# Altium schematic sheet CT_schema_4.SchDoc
size 382 x 218 mm
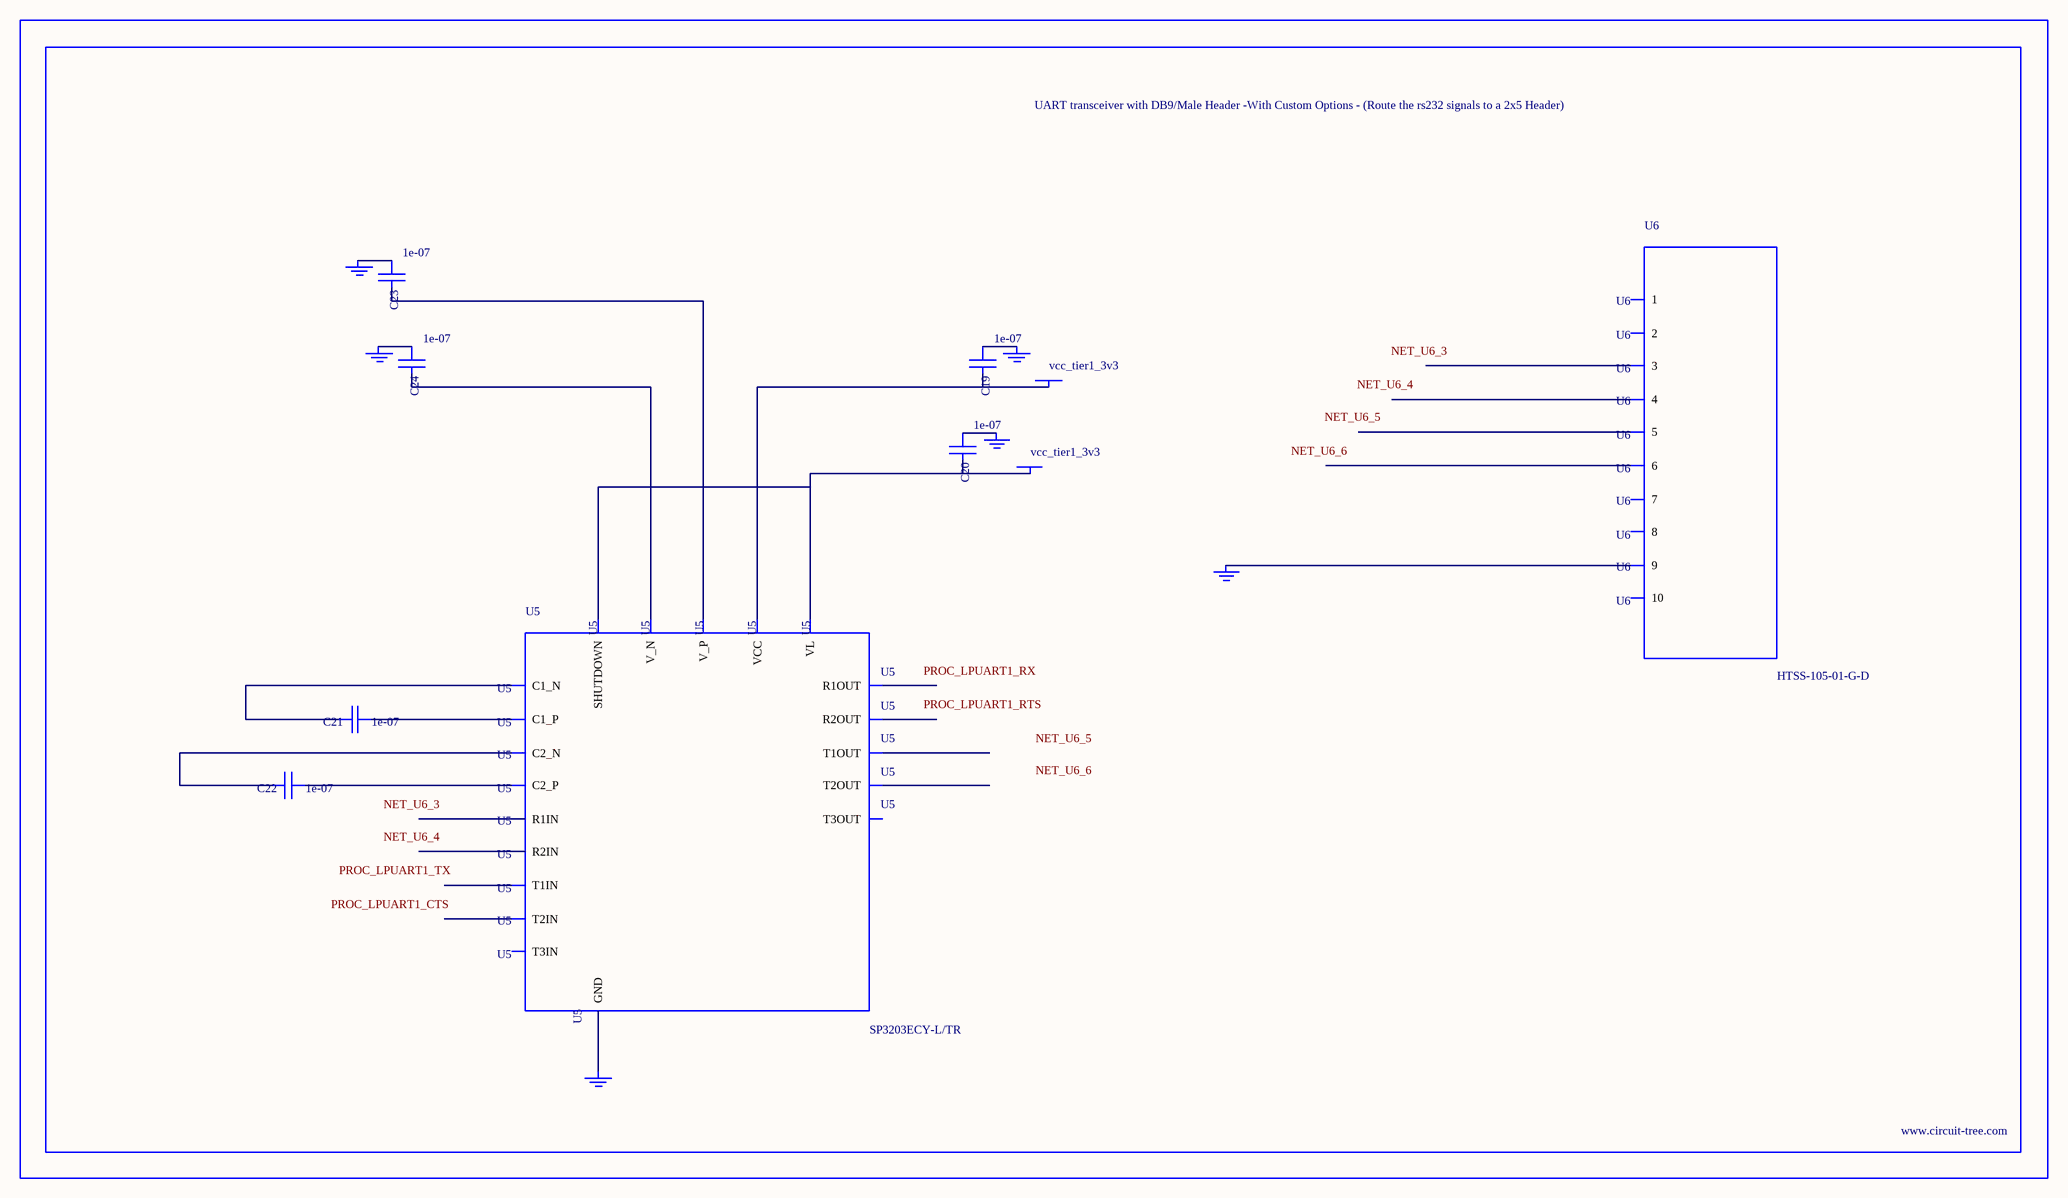
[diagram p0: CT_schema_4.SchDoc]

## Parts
BORDER3  (no value)
C19  1e-07  [C0402]
C20  1e-07  [C0402]
C21  1e-07  [C0402]
C22  1e-07  [C0402]
C23  1e-07  [C0402]
C24  1e-07  [C0402]
GND_INSTANCE_3_0  (no value)
GND_INSTANCE_3_1  (no value)
GND_INSTANCE_3_2  (no value)
GND_INSTANCE_3_3  (no value)
GND_INSTANCE_3_4  (no value)
GND_INSTANCE_3_5  (no value)
POWER_INSTANCE_3_0  vcc_tier1_3v3
POWER_INSTANCE_3_1  vcc_tier1_3v3
U5  SP3203ECY-L/TR  [TSSOP20-I]
U6  HTSS-105-01-G-D  [HTSS-105-01-G-D]

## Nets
NetC19_1: C19.1 GND_INSTANCE_3_3.0(GND)
NetC19_2: C19.2 POWER_INSTANCE_3_1.0(PWR) U5.19(VCC)
NetC20_1: C20.1 GND_INSTANCE_3_2.0(GND)
NetC20_2: C20.2 POWER_INSTANCE_3_0.0(PWR) U5.12(VL) U5.20(SHUTDOWN)
NetC21_1: C21.1 U5.1(C1_P)
NetC21_2: C21.2 U5.3(C1_N)
NetC22_1: C22.1 U5.4(C2_P)
NetC22_2: C22.2 U5.5(C2_N)
NetC23_1: C23.1 GND_INSTANCE_3_0.0(GND)
NetC23_2: C23.2 U5.2(V_P)
NetC24_1: C24.1 GND_INSTANCE_3_1.0(GND)
NetC24_2: C24.2 U5.6(V_N)
NetGND_INSTANCE_3_4_0: GND_INSTANCE_3_4.0(GND) U5.18(GND)
NetGND_INSTANCE_3_5_0: GND_INSTANCE_3_5.0(GND) U6.9

Not connected (* = marked no-connect by the designer): U5 7(T1IN) 8(T2IN) 9(T3IN) 10(R2OUT) 11(R1OUT) 13(R2IN) 14(R1IN) 15(T3OUT) 16(T2OUT) 17(T1OUT); U6 1 2 3 4 5 6 7 8 10

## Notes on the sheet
- Labels drawn without touching a wire or pin: NET_U6_3, NET_U6_4, NET_U6_5, NET_U6_6, PROC_LPUART1_CTS, PROC_LPUART1_RTS, PROC_LPUART1_RX, PROC_LPUART1_TX

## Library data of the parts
BORDER3 = BORDER_PAGE3
C19-C24 = C0402C104K3RACTU
GND_INSTANCE_3_0-GND_INSTANCE_3_5 = GND
POWER_INSTANCE_3_0 POWER_INSTANCE_3_1 = PWR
